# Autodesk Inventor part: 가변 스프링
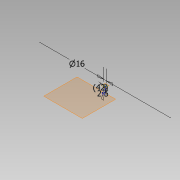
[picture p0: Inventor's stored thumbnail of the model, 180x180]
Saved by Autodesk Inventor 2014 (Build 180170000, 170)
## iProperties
Created: 2015-05
Part Number: 가변 스프링
Material: Generic
Document SubType Name: Modeling
Designer: Administrator
Density: 1 g/cm^3
Appearance: Default
Author: Administrator
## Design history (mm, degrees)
sketch "스케치1"
  geometry: L1 (0, 0)-(-8, 0); L2 (-8, 0)-(-8, 42); L3 (-8, 42)-(0, 42); L4 (0, 42)-(0, 0); C1 r 1.25 at (-8, 0)
  constraints: 8 end point, 2 parallel, 1 centre point, 1 coincident, 1 horizontal, 1 perpendicular, 1 other
  dimensions: "d0" = 16 diameter of L2 L4; "d1" = 42 distance between parallel lines of L1 L3 (derived); "d2" = 2.5 diameter of C1
feature "코일1" pitch "d3" = 10; turns "d5" = 6; dims "d4" = 42 (= d1), "d6" = 0, angle "d7" = 90 deg, angle "d8" = 90 deg, "d9" = 0, "d10" = 0
node "작업 평면1"
node "작업 평면2"
sketch "스케치3"
  geometry: L1 (-9.25, 0)-(-6.75, 0) reference
  constraints: 1 horizontal alignment
extrude "돌출2" cut sketch "스케치3" stored distance "d13" = 10; taper "d14" = 0 deg
node "작업 평면3"
sketch "스케치4"
  geometry: L1 (-6.75, 0)-(-9.25, 0) reference
  constraints: 1 horizontal alignment
extrude "돌출3" cut sketch "스케치4" stored distance "d15" = 10; taper "d16" = 0 deg
node "솔리드1"
node "절단 모서리 투영2"
node "절단 모서리 투영3"
